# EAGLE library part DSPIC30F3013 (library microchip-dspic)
dsPIC Sensor DSP
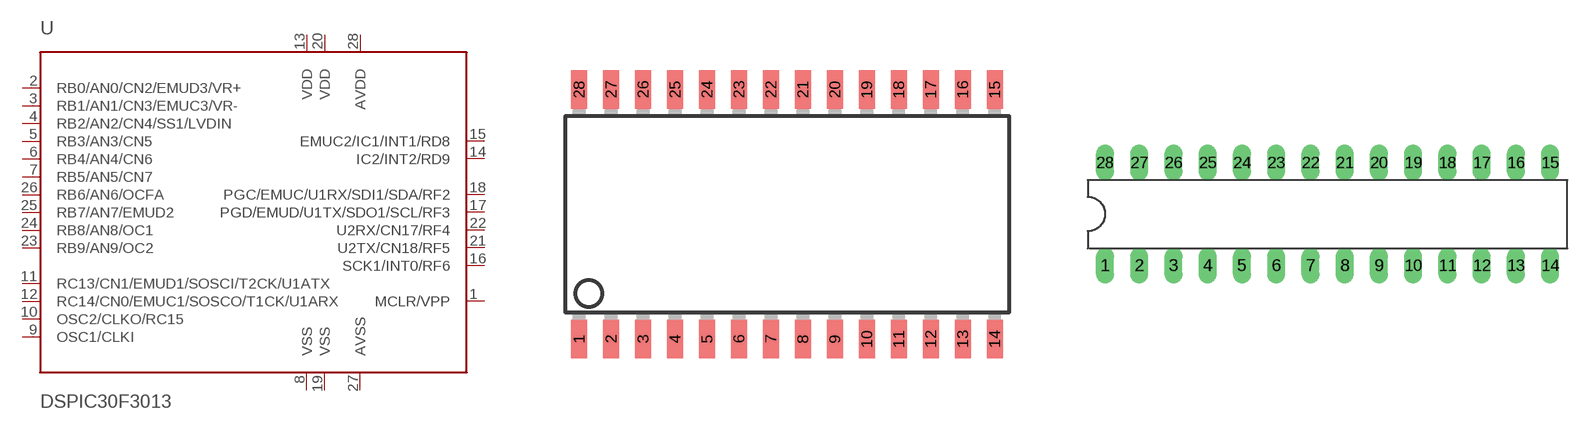
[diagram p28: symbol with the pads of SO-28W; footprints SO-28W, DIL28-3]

Designator prefix -

## DSPIC30F3013/SO  [SO-28W]
1  MCLR/VPP  in
2  RB0/AN0/CN2/EMUD3/VR+
3  RB1/AN1/CN3/EMUC3/VR-
4  RB2/AN2/CN4/SS1/LVDIN
5  RB3/AN3/CN5
6  RB4/AN4/CN6
7  RB5/AN5/CN7
8  VSS  pwr
9  OSC1/CLKI  in
10  OSC2/CLKO/RC15
11  RC13/CN1/EMUD1/SOSCI/T2CK/U1ATX
12  RC14/CN0/EMUC1/SOSCO/T1CK/U1ARX
13  VDD  pwr
14  IC2/INT2/RD9
15  EMUC2/IC1/INT1/RD8
16  SCK1/INT0/RF6
17  PGD/EMUD/U1TX/SDO1/SCL/RF3
18  PGC/EMUC/U1RX/SDI1/SDA/RF2
19  VSS  pwr
20  VDD  pwr
21  U2TX/CN18/RF5
22  U2RX/CN17/RF4
23  RB9/AN9/OC2
24  RB8/AN8/OC1
25  RB7/AN7/EMUD2
26  RB6/AN6/OCFA
27  AVSS  pwr
28  AVDD  pwr

## DSPIC30F3013/SP  [DIL28-3]
Pads as for SO-28W

## DSPIC30F3013/ML  [QFN44-8X8]
1  PGC/EMUC/U1RX/SDI1/SDA/RF2
2  VSS  pwr
4  VDD  pwr
7  U2TX/CN18/RF5
9  U2RX/CN17/RF4
10  RB9/AN9/OC2
11  RB8/AN8/OC1
12  RB7/AN7/EMUD2
14  RB6/AN6/OCFA
16  AVSS  pwr
17  AVDD  pwr
18  MCLR/VPP  in
19  RB0/AN0/CN2/EMUD3/VR+
20  RB1/AN1/CN3/EMUC3/VR-
23  RB2/AN2/CN4/SS1/LVDIN
25  RB3/AN3/CN5
26  RB4/AN4/CN6
27  RB5/AN5/CN7
30  VSS  pwr
32  OSC1/CLKI  in
33  OSC2/CLKO/RC15
34  RC13/CN1/EMUD1/SOSCI/T2CK/U1ATX
35  RC14/CN0/EMUC1/SOSCO/T1CK/U1ARX
36  VDD  pwr
37  IC2/INT2/RD9
42  EMUC2/IC1/INT1/RD8
43  SCK1/INT0/RF6
44  PGD/EMUD/U1TX/SDO1/SCL/RF3

## Footprint SO-28W (pad centres in mm)
Small Outline Wide Plastic Gull Wing 300-mil body, package type SO
smd 0.635 x 1.524: 1 -7.62,-4.953; 2 -6.35,-4.953; 3 -5.08,-4.953; 4 -3.81,-4.953; 5 -2.54,-4.953; 6 -1.27,-4.953; 7 0,-4.953; 8 1.27,-4.953; 9 2.54,-4.953; 10 3.81,-4.953; 11 5.08,-4.953; 12 6.35,-4.953; 13 7.62,-4.953; 14 8.89,-4.953; 15 8.89,4.953; 16 7.62,4.953; 17 6.35,4.953; 18 5.08,4.953; 19 3.81,4.953; 20 2.54,4.953; 21 1.27,4.953; 22 0,4.953; 23 -1.27,4.953; 24 -2.54,4.953; 25 -3.81,4.953; 26 -5.08,4.953; 27 -6.35,4.953; 28 -7.62,4.953

## Footprint DIL28-3 (pad centres in mm)
Dual In Line package type P
drill 0.813 long: 1 -16.51,-3.81; 2 -13.97,-3.81; 3 -11.43,-3.81; 4 -8.89,-3.81; 5 -6.35,-3.81; 6 -3.81,-3.81; 7 -1.27,-3.81; 8 1.27,-3.81; 9 3.81,-3.81; 10 6.35,-3.81; 11 8.89,-3.81; 12 11.43,-3.81; 13 13.97,-3.81; 14 16.51,-3.81; 15 16.51,3.81; 16 13.97,3.81; 17 11.43,3.81; 18 8.89,3.81; 19 6.35,3.81; 20 3.81,3.81; 21 1.27,3.81; 22 -1.27,3.81; 23 -3.81,3.81; 24 -6.35,3.81; 25 -8.89,3.81; 26 -11.43,3.81; 27 -13.97,3.81; 28 -16.51,3.81

## Footprint QFN44-8X8 (pad centres in mm)
Quad Flat No Lead
smd 0.6 x 0.37: 1 3.825,-3.25; 2 3.825,-2.6; 3 3.825,-1.95; 4 3.825,-1.3; 5 3.825,-0.65; 6 3.825,0; 7 3.825,0.65; 8 3.825,1.3; 9 3.825,1.95; 10 3.825,2.6; 11 3.825,3.25; 23 -3.825,3.25; 24 -3.825,2.6; 25 -3.825,1.95; 26 -3.825,1.3; 27 -3.825,0.65; 28 -3.825,0; 29 -3.825,-0.65; 30 -3.825,-1.3; 31 -3.825,-1.95; 32 -3.825,-2.6; 33 -3.825,-3.25
smd 0.37 x 0.6: 12 3.25,3.825; 13 2.6,3.825; 14 1.95,3.825; 15 1.3,3.825; 16 0.65,3.825; 17 0,3.825; 18 -0.65,3.825; 19 -1.3,3.825; 20 -1.95,3.825; 21 -2.6,3.825; 22 -3.25,3.825; 34 -3.25,-3.825; 35 -2.6,-3.825; 36 -1.95,-3.825; 37 -1.3,-3.825; 38 -0.65,-3.825; 39 0,-3.825; 40 0.65,-3.825; 41 1.3,-3.825; 42 1.95,-3.825; 43 2.6,-3.825; 44 3.25,-3.825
